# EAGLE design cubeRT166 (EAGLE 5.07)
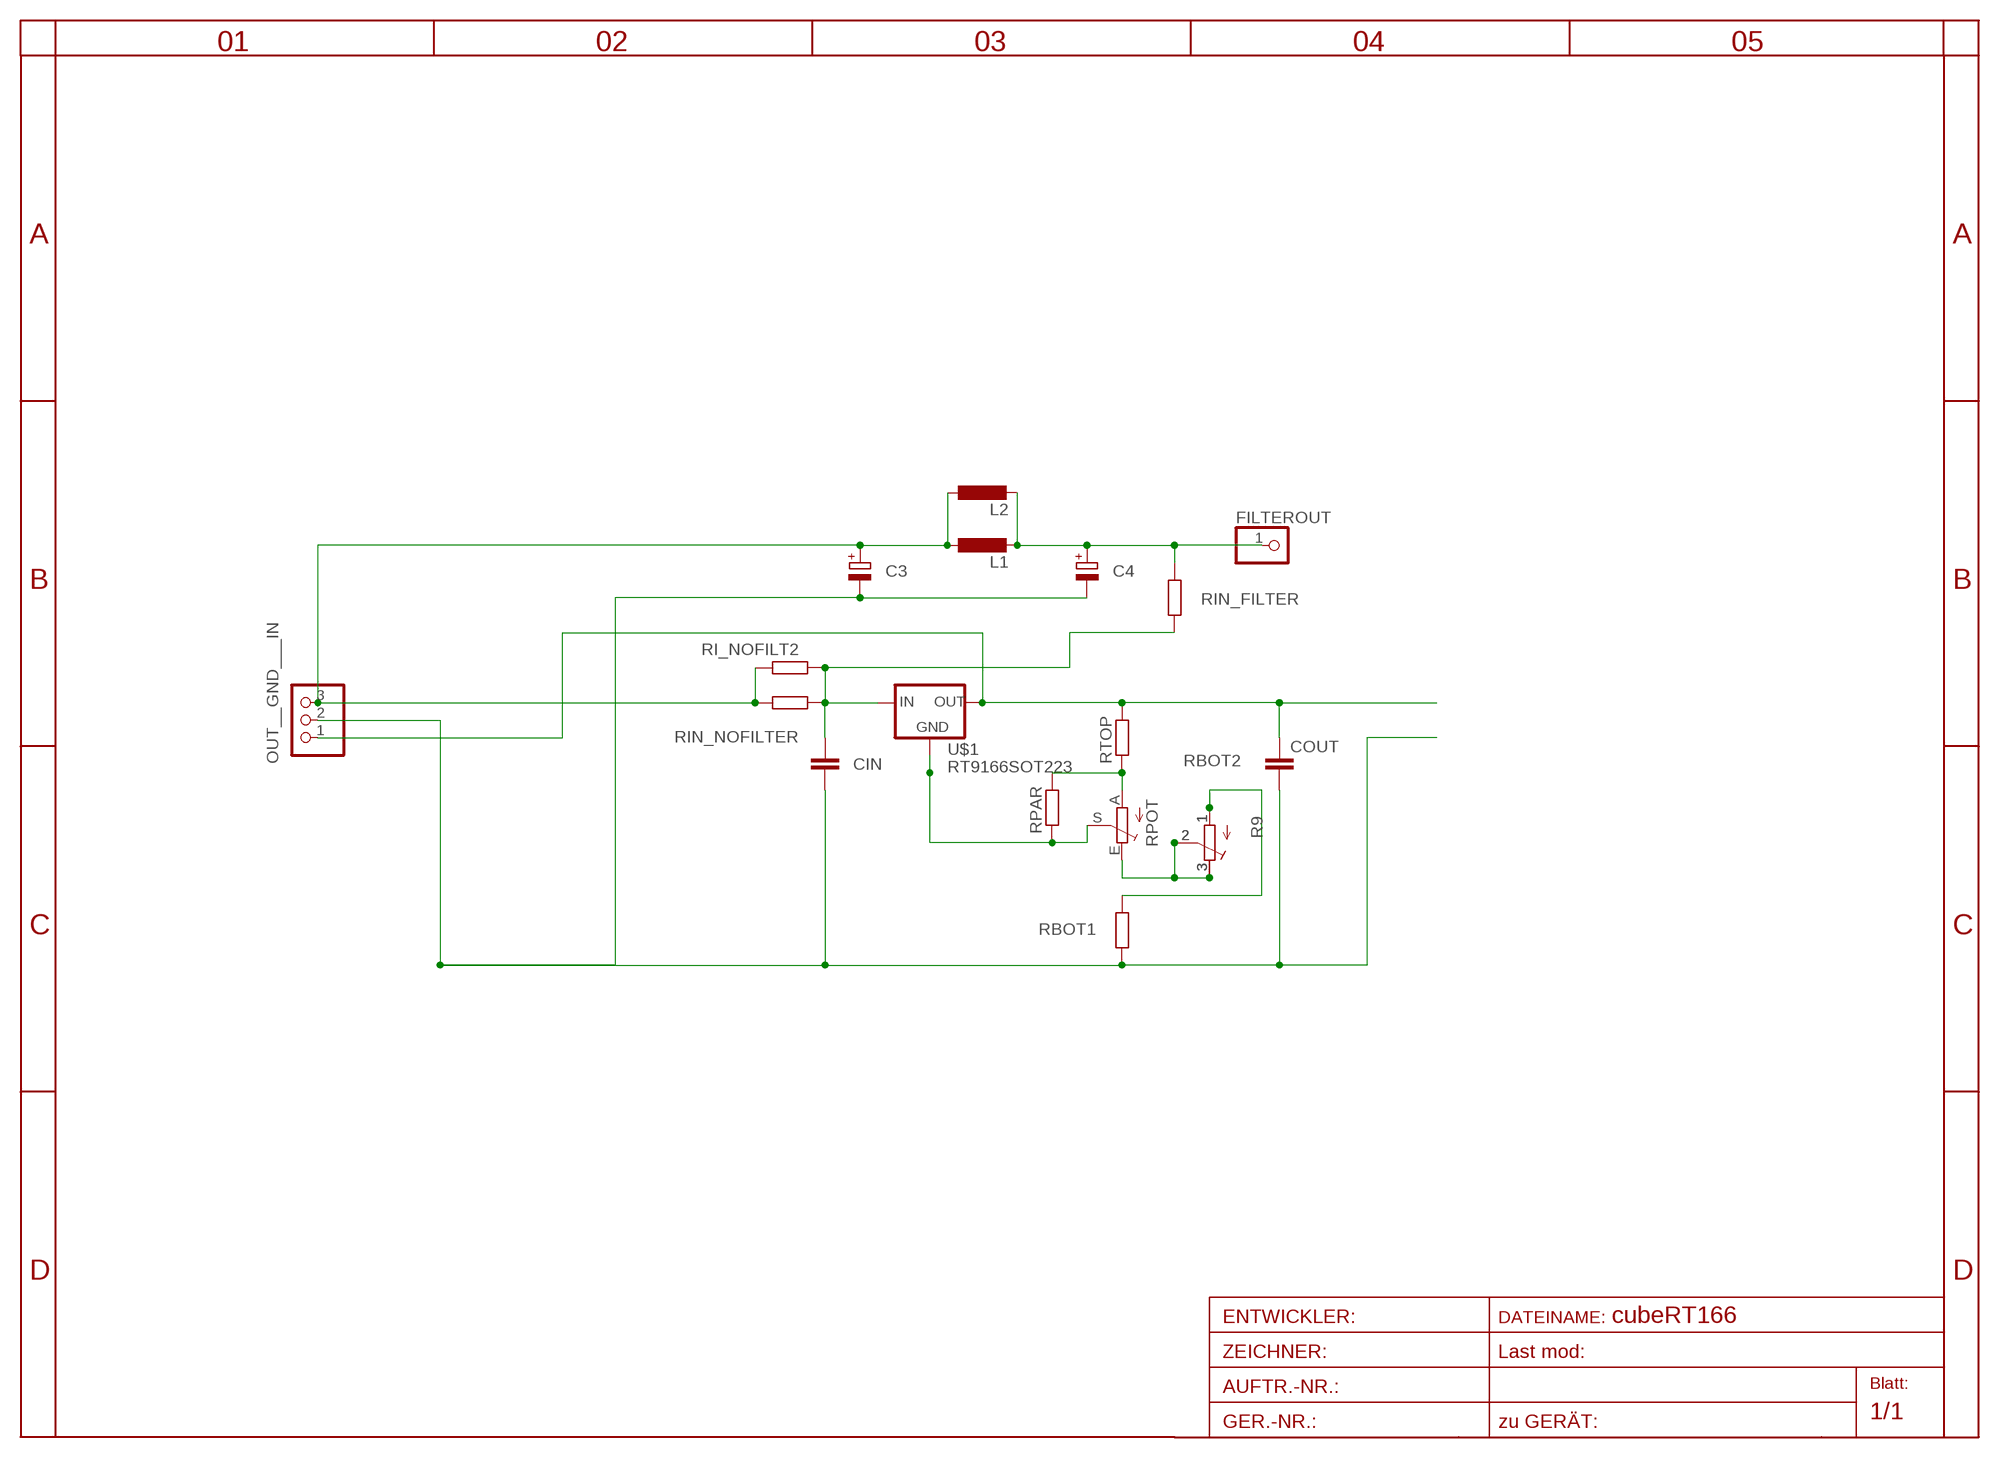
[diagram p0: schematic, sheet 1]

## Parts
C3  CPOL-EUE  [PANASONIC_E]
C4  CPOL-EUE  [PANASONIC_E]
CIN  C-EUC1206  [C1206]
COUT  C-EUC1206  [C1206]
FILTEROUT  PINHD-1X11X0.4  [1X01]
L1  L-EUPIS2816  [PIS2816]
L2  L-EUOPEN  [OPEN5]
OUT__GND___IN  PINHD-1X3  [1X03]
R9  R-TRIMM3374  [RTRIM3374]
RBOT1  R-EU_R0805  [R0805]
RBOT2  R-TRIMM3202  [RTRIM3202]
RI_NOFILT2  R-EU_R0805  [R0805]
RIN_FILTER  R-EU_R0805  [R0805]
RIN_NOFILTER  R-EU_R0805  [R0805]
RPAR  R-EU_R0805  [R0805]
RPOT  TRIM_EU-RAND160  [RANDL]
RTOP  R-EU_R0805  [R0805]
U$1  RT9166SOT223  [SOT223]

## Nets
ADJ: RPAR.1 RPOT.S U$1.2(GND) U$1.4(GND1)
GND: C3.- C4.- CIN.2 COUT.2 OUT__GND___IN.2 RBOT1.1
IN: CIN.1 RI_NOFILT2.1 RIN_FILTER.2 RIN_NOFILTER.1 U$1.3(IN)
N$1: C3.+ L1.1 L2.1 OUT__GND___IN.3 RI_NOFILT2.2 RIN_NOFILTER.2
N$2: RPAR.2 RPOT.A RTOP.1
N$3: C4.+ FILTEROUT.1 L1.2 L2.2 RIN_FILTER.1
N$4: R9.2(S) R9.3(A) RBOT2.2(S) RBOT2.3(A) RPOT.E
N$5: R9.1(E) RBOT1.2 RBOT2.1(E)
OUT: COUT.1 OUT__GND___IN.1 RTOP.2 U$1.1(OUT)

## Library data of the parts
C3 C4 = rcl:CPOL-EU: POLARIZED CAPACITOR, European symbol
CIN COUT = rcl:C-EU: CAPACITOR, European symbol
FILTEROUT = pinhead:PINHD-1X1: PIN HEADER
L1 L2 = rcl:L-EU: INDUCTOR, European symbol
OUT__GND___IN = pinhead:PINHD-1X3: PIN HEADER
R9 RBOT2 = rcl:R-TRIMM: Trimm resistor
RBOT1 RI_NOFILT2 RIN_FILTER RIN_NOFILTER RPAR RTOP = rcl:R-EU_: RESISTOR, European symbol
RPOT = pot:TRIM_EU-: POTENTIOMETER
U$1 = v-reg:RT9166

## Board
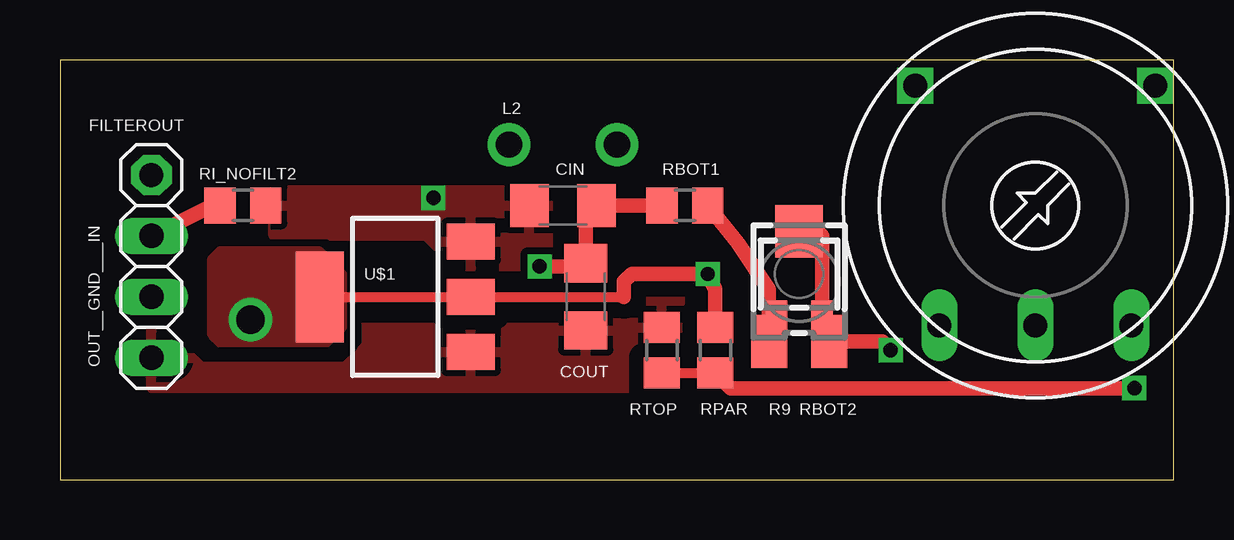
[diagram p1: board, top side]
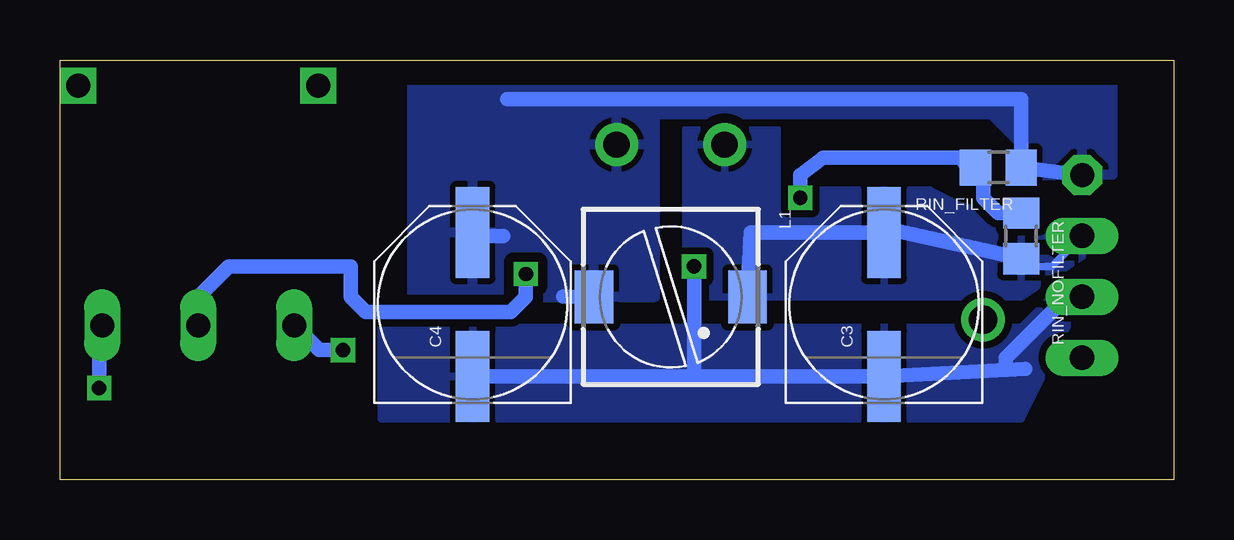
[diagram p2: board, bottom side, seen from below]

Size 46.4 x 17.5 mm. Coordinates in mm from the lower left corner, seen from the top.
Outline: 0,0 46.4,0 46.4,17.5 0,17.5 0,0
Copper layers (1*16): Top 0.035mm / dielectric 1.5mm / Bottom 0.035mm
Design rules "default *": minimum track width 10mil, minimum drill 20mil, track to track 8mil, track to pad 8mil, pad to pad 8mil, via to via 8mil, smd to smd 8mil, copper to edge 40mil, drill to drill 8mil, minimum pad ring 1mil, minimum via ring 8mil, stop-mask expansion 4mil, vias tented up to drill 0mil, thermal gap 10mil

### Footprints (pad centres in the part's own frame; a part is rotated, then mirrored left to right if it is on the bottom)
PANASONIC_E = smd 3.8 x 1.4: + 3,0; - -3,0
C1206 = smd 1.6 x 1.8: 1 -1.4,0; 2 1.4,0
1X01 = drill 1 pad 1.676 octagon: 1 0,0
PIS2816 = smd 2.2 x 1.6: 1 0,3.2; 2 0,-3.2
OPEN5 = drill 1.1 pad 1.778 round: 1 -2.25,0; 2 2.25,0
1X03 = drill 1.016 long: 1 -2.54,0; 2 0,0; 3 2.54,0
RTRIM3374 = smd 1.5 x 2.2: 1 -1.25,-2.5; 3 1.25,-2.5 | smd 1.98 x 2.17: 2 0,2.1
R0805 = smd 1.3 x 1.5: 1 -0.95,0; 2 0.95,0
RTRIM3202 = smd 0.9 x 1.3: 1 -0.95,-1.75; 3 0.95,-1.75 | smd 1.6 x 1.4: 2 0,1.6
RANDL = drill 1 long: A -4,5; E 4,5; S 0,5 | drill 1 square: P$1 -5,-5; P$2 5,-5
SOT223 = smd 1.5 x 2: 1 -2.3,-3.15; 2 0,-3.15; 3 2.3,-3.15 | smd 3.8 x 2: 4 0,3.15

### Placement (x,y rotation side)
C3  12.06,7.3 90 bottom
C4  29.21,7.3 90 bottom
CIN  20.95,11.43 0 top
COUT  21.91,7.62 90 top
FILTEROUT  3.81,12.7 0 top
L1  20.95,7.62 270 bottom
L2  20.95,13.97 0 top
OUT__GND___IN  3.81,7.62 90 top
R9  30.8,8.26 0 top
RBOT1  26.04,11.43 0 top
RBOT2  30.8,8.57 0 top
RI_NOFILT2  7.62,11.43 180 top
RIN_FILTER  7.3,13.02 180 bottom
RIN_NOFILTER  6.35,10.16 270 bottom
RPAR  27.3,5.4 270 top
RPOT  40.64,11.43 180 top
RTOP  25.08,5.4 90 top
U$1  13.97,7.62 90 top

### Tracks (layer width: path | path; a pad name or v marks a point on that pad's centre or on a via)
ADJ  (via drill 0.6, 1.2)
  Top 0.406: U$1.4 U$1.2 23.5,7.62
  Top 0.61: RPAR.1 27.3,7.94 v26.99,8.57 23.81,8.57 23.5,8.26 23.5,7.62
  Bottom 0.61: v26.99,8.57 26.99,7.62 27.62,6.99 33.66,6.99 34.29,7.62 34.29,8.89 39.37,8.89 40.64,7.62 RPOT.S
  other vias: 7.94,6.67
  pour Top (no thermals): 6.35,6.03 6.35,9.21 6.67,9.53 10.79,9.53 11.75,8.57 11.75,6.35 11.11,5.71 6.67,5.71
GND  (via drill 0.6)
  Top 0.406: 21.59,8.89 21.59,9.02 COUT.2 | 21.91,10.79 CIN.2
  Top 0.61: v19.98,8.89 21.59,8.89 | COUT.2 21.91,10.79 | CIN.2 RBOT1.1
  Bottom 0.61: 19.98,4.3 C3.- 6.96,4.58 | 19.98,4.3 C4.- | 6.96,4.58 6.17,4.62 | 19.98,4.3 v19.98,8.89 | OUT__GND___IN.2 4.45,7.62 6.99,5.08 6.99,4.61 6.96,4.58
  pour Bottom (isolate 0.305, rank 3): 3.81,7.62 5.08,7.62 6.35,6.35 33.02,6.35 33.02,2.54 6.35,2.54
IN  (via drill 0.6)
  Bottom 0.61: v15.56,11.75 15.56,12.7 14.61,13.43 8.89,13.43 8.57,13.02 RIN_FILTER.2 7.94,12.7 7.94,11.75 7.3,11.11 RIN_NOFILTER.1
  pour Top (isolate 0.305, rank 2): 20.32,12.06 20.32,8.89 16.51,8.89 15.24,10.16 8.89,10.16 8.89,12.06
N$1
  Top 0.61: RI_NOFILT2.2 6.35,11.43 OUT__GND___IN.3
  Bottom 0.305: OUT__GND___IN.3 5.08,8.89 6.03,8.89 RIN_NOFILTER.2
  Bottom 0.61: RIN_NOFILTER.2 12.06,10.48 C3.+ 17.61,10.3 L1.1
  pour Bottom (isolate 0.305, rank 2): 2.54,10.16 6.35,7.62 20.32,7.62 20.32,14.61 16.51,14.61 16.51,12.06 10.16,12.06 8.89,11.43
N$2  (via drill 0.6)
  Top 0.406: RTOP.1 RPAR.2
  Top 0.61: RPAR.2 27.94,3.81 v44.77,3.81
  Bottom 0.61: v44.77,3.81 44.77,6.24 RPOT.A
N$3
  Bottom 0.61: L1.2 25.43,7.64 | 27.94,10.16 28.75,10.16 | 27.77,15.88 6.35,15.88 6.35,13.97 RIN_FILTER.1 FILTEROUT.1
  pour Bottom (isolate 0.406): 2.54,16.51 31.75,16.51 31.75,7.62 21.59,7.62 21.59,15.24 7.62,15.24 6.35,13.97 6.35,12.7 2.54,12.7
N$4  (via drill 0.6)
  Top 0.61: 31.75,6.35 31.75,6.05 R9.3 34.25,5.75 v34.61,5.4 | 31.75,6.35 31.75,10.16 31.55,10.36 R9.2 RBOT2.2 | RBOT2.3 31.75,6.35
  Bottom 0.61: v34.61,5.4 35.61,5.4 RPOT.E
N$5
  Top 0.61: RBOT1.2 28.26,9.84 29.53,7.94 29.53,6.35 | 29.53,6.35 29.53,5.78 R9.1 | RBOT2.1 29.85,6.67 29.53,6.35
OUT
  pour Top (isolate 0.61, rank 3): 3.81,6.35 21.59,6.35 22.86,7.62 26.67,7.62 26.67,5.08 25.4,3.81 3.81,3.81

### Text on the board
tStop: MICHAEL5.net
bStop: MICHAEL5.net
